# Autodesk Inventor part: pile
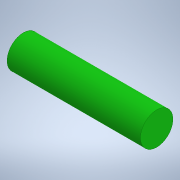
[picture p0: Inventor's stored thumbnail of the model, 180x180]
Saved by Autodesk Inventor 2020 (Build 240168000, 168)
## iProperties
Created: 2021-10
Part Number: pile
Material: Générique
Document SubType Name: Modeling
Designer: bruno
Density: 1 g/cm^3
Appearance: Vert foncé
Author: bruno
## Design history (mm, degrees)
sketch "Esquisse1"
  geometry: C1 r 9 at (0, 0); 1 further point
  constraints: 1 centre point, 1 coincident
  dimensions: "d0" = 18 diameter of C1
extrude "Extrusion1" new body sketch "Esquisse1" distance "d1" = 74; taper "d2" = 0 deg
node "Solide1"
